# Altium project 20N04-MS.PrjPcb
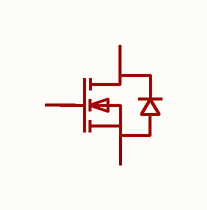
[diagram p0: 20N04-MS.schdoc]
1 sheet, 1 parts. Net scope: global (net labels, ports and power ports of the same name join across sheets).

## Sheet 20N04-MS.schdoc
size 127 x 101 mm

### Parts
Q?  20n04-ms  [SOT-89-3_L4.5-W2.5-P1.50-LS4.1-BR]  (value not drawn)

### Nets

Not connected (* = marked no-connect by the designer): Q? 1(G) 2(D) 3(S)

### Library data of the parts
Q? = 20n04-ms: 数量:1个N沟道;漏源电压(Vdss):40V;连续漏极电流(Id):15A;导通电阻(RDS(on)):25mΩ@4.5V;耗散功率(Pd):1.5W;阈值电压(Vgs(th)):2.5V;; Manufacturer: MSKSEMI(美森科); AddInBom: yes; ModelId: 6db690b7897d4d18a30d90c1b89525ee; ModelName: SOT-89-3_L4.3-W2.5-H1.6-LS4.1-P1.50; ModelTransform: 161.417,169.291,0,180,0,0,-14.134,0,0; Number: 1个N沟道; Drain to Source Voltage: 40V; Current - Continuous Drain(Id): 15A; Pd - Power Dissipation: 1.5W; Gate Threshold Voltage (Vgs(th)): 2.5V; Gate Charge(Qg): 12nC@10V; Type: N沟道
